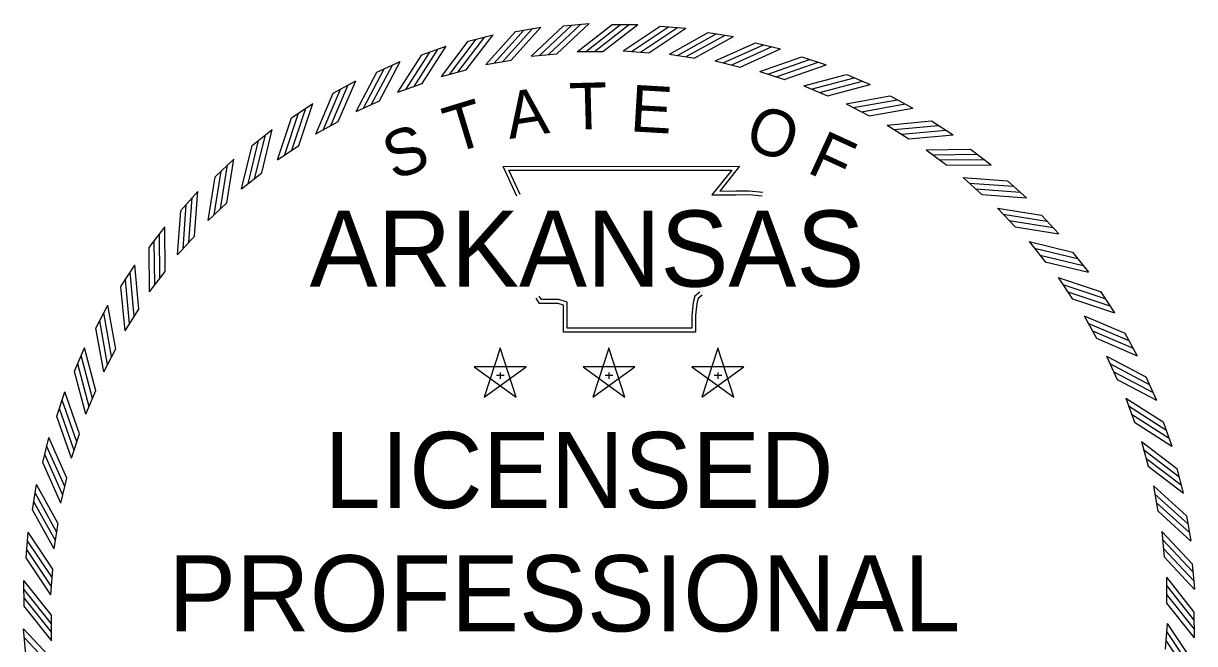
# Model space of a CAD drawing. Extents: x -129 to 14744569, y -102 to 1829048.
# Drawn here: x -104.853 to -102.787, y -99.681 to -98.587 of the extents above; entities that cross this region are included whole.
import ezdxf

# ---------------------------------------------------------------- set-up
doc = ezdxf.new("R2010")
doc.units = 0
doc.layers.add('STAMP', color=7, linetype='Continuous')

msp = doc.modelspace()

# ---------------------------------------------------------------- linework, layer by layer
at = {"layer": 'STAMP'}
for p, q in [((-103.9843, -98.6012), (-103.9398, -98.5934)), ((-103.8996, -98.5911), (-103.8546, -98.587)), ((-103.814, -98.5886), (-103.7687, -98.5886)), ((-103.7292, -98.592), (-103.6841, -98.5953)), ((-104.0679, -98.6183), (-104.0241, -98.6068)), ((-103.6447, -98.603), (-103.6, -98.61)), ((-104.1497, -98.6422), (-104.1071, -98.6272)), ((-103.8757, -98.6367), (-103.8304, -98.6367)), ((-103.7943, -98.6355), (-103.7491, -98.6388)), ((-103.5613, -98.6209), (-103.5173, -98.6316)), ((-104.2293, -98.6728), (-104.1881, -98.6543)), ((-104.0368, -98.6594), (-103.9921, -98.6515)), ((-103.9567, -98.6447), (-103.9115, -98.6406)), ((-103.7131, -98.6409), (-103.6683, -98.648)), ((-103.6327, -98.6531), (-103.5886, -98.6638)), ((-103.4797, -98.6457), (-103.4368, -98.66)), ((-104.1153, -98.6806), (-104.0715, -98.669)), ((-103.5535, -98.6718), (-103.5104, -98.6861)), ((-103.4004, -98.6771), (-103.3588, -98.6948)), ((-104.3061, -98.7099), (-104.2665, -98.688)), ((-104.1919, -98.7082), (-104.1491, -98.6931)), ((-103.4761, -98.697), (-103.4344, -98.7149)), ((-103.324, -98.7149), (-103.284, -98.7361)), ((-104.3796, -98.7532), (-104.342, -98.7281)), ((-104.2659, -98.7421), (-104.2245, -98.7235)), ((-103.4011, -98.7286), (-103.361, -98.7498)), ((-104.3368, -98.7819), (-104.2972, -98.76)), ((-103.2509, -98.7589), (-103.2128, -98.7833)), ((-104.4493, -98.8024), (-104.4138, -98.7743)), ((-103.3289, -98.7662), (-103.2907, -98.7906)), ((-104.4043, -98.8275), (-104.3665, -98.8023)), ((-103.2601, -98.8096), (-103.224, -98.8371)), ((-103.1818, -98.8088), (-103.1458, -98.8363)), ((-104.5146, -98.8572), (-104.4816, -98.8262)), ((-104.4677, -98.8784), (-104.4322, -98.8503)), ((-103.1951, -98.8586), (-103.1614, -98.889)), ((-103.117, -98.8643), (-103.0834, -98.8946)), ((-104.5752, -98.9171), (-104.5449, -98.8836)), ((-104.5267, -98.9345), (-104.4936, -98.9035)), ((-103.1344, -98.9128), (-103.1033, -98.9459)), ((-103.057, -98.9249), (-103.0261, -98.9579)), ((-104.6307, -98.9819), (-104.6032, -98.946)), ((-104.5809, -98.9952), (-104.5505, -98.9616)), ((-103.0783, -98.9718), (-103.0501, -99.0073)), ((-103.0022, -98.9902), (-102.9741, -99.0257)), ((-104.6806, -99.0511), (-104.6562, -99.013)), ((-104.6299, -99.0602), (-104.6024, -99.0242)), ((-103.0273, -99.0352), (-103.0022, -99.073)), ((-102.953, -99.0599), (-102.9279, -99.0975)), ((-104.7246, -99.1241), (-104.7034, -99.0841)), ((-104.6733, -99.129), (-104.6489, -99.0908)), ((-102.9818, -99.1027), (-102.9598, -99.1423)), ((-102.9097, -99.1334), (-102.8879, -99.173)), ((-104.7624, -99.2005), (-104.7447, -99.1589)), ((-104.7109, -99.2012), (-104.6897, -99.1611)), ((-104.0117, -99.1594), (-104.04, -99.2462)), ((-103.9835, -99.2462), (-104.0116, -99.1593)), ((-103.8198, -99.1594), (-103.8481, -99.2462)), ((-103.7916, -99.2462), (-103.8197, -99.1593)), ((-103.6279, -99.1594), (-103.6562, -99.2462)), ((-103.5997, -99.2462), (-103.6278, -99.1593)), ((-102.9419, -99.1736), (-102.9233, -99.215)), ((-103.966, -99.1926), (-104.0574, -99.1925)), ((-104.0573, -99.1926), (-103.9835, -99.2463)), ((-104.0399, -99.2462), (-103.9659, -99.1926)), ((-103.7741, -99.1926), (-103.8655, -99.1925)), ((-103.8654, -99.1926), (-103.7916, -99.2463)), ((-103.848, -99.2462), (-103.774, -99.1926)), ((-103.5822, -99.1926), (-103.6736, -99.1925)), ((-103.6735, -99.1926), (-103.5997, -99.2463)), ((-103.6561, -99.2462), (-103.5821, -99.1926)), ((-104.0182, -99.2071), (-104.0046, -99.2071)), ((-104.0116, -99.2023), (-104.0116, -99.2137)), ((-103.8263, -99.2071), (-103.8127, -99.2071)), ((-103.8197, -99.2023), (-103.8197, -99.2137)), ((-103.6344, -99.2071), (-103.6208, -99.2071)), ((-103.6278, -99.2023), (-103.6278, -99.2137)), ((-102.8727, -99.2102), (-102.8541, -99.2514)), ((-104.7939, -99.2798), (-104.7796, -99.2369)), ((-104.7425, -99.2762), (-104.7246, -99.2345)), ((-102.9081, -99.2476), (-102.8929, -99.2904)), ((-102.8421, -99.2898), (-102.827, -99.3324)), ((-104.8186, -99.3614), (-104.8079, -99.3175)), ((-104.7677, -99.3536), (-104.7534, -99.3106)), ((-102.8804, -99.3242), (-102.8689, -99.368)), ((-102.8182, -99.3716), (-102.8067, -99.4154)), ((-104.8365, -99.4448), (-104.8295, -99.4001)), ((-104.7864, -99.4328), (-104.7757, -99.3887)), ((-102.8592, -99.4028), (-102.8514, -99.4474)), ((-102.8011, -99.4552), (-102.7932, -99.4997)), ((-104.8475, -99.5294), (-104.8442, -99.4843)), ((-104.7986, -99.5133), (-104.7915, -99.4685)), ((-102.8446, -99.4828), (-102.8404, -99.528)), ((-102.791, -99.5399), (-102.7868, -99.5849)), ((-104.8515, -99.6146), (-104.8519, -99.5693)), ((-104.804, -99.5945), (-104.8007, -99.5493)), ((-102.8366, -99.5638), (-102.8362, -99.6091)), ((-104.8028, -99.6759), (-104.8032, -99.6305)), ((-102.7879, -99.6251), (-102.7875, -99.6703)), ((-102.8353, -99.6452), (-102.8387, -99.6904)), ((-104.8484, -99.6998), (-104.8525, -99.6547))]:
    msp.add_line(p, q, dxfattribs=at)
for points in [[(-104.007, -98.654), (-103.9546, -98.5958)], [(-103.9922, -98.6515), (-103.9397, -98.5934)], [(-103.9567, -98.6448), (-103.8997, -98.5912)], [(-103.9422, -98.6436), (-103.8852, -98.59)], [(-103.9266, -98.6418), (-103.8696, -98.5882)], [(-103.9116, -98.6405), (-103.8546, -98.5869)], [(-103.8758, -98.6368), (-103.814, -98.5886)], [(-103.8612, -98.6369), (-103.7995, -98.5888)], [(-103.8455, -98.6366), (-103.7838, -98.5884)], [(-103.8304, -98.6367), (-103.7687, -98.5886)], [(-103.7944, -98.6355), (-103.7293, -98.592)], [(-103.7799, -98.6367), (-103.7148, -98.5932)], [(-103.7642, -98.6375), (-103.6991, -98.594)], [(-103.7492, -98.6388), (-103.6841, -98.5953)], [(-104.1154, -98.6806), (-104.0679, -98.6184)], [(-104.1013, -98.6771), (-104.0538, -98.6148)], [(-104.0861, -98.6727), (-104.0387, -98.6105)], [(-104.0715, -98.669), (-104.0241, -98.6068)], [(-104.0368, -98.6594), (-103.9844, -98.6013)], [(-104.0224, -98.657), (-103.97, -98.5989)], [(-103.7132, -98.641), (-103.6447, -98.603)], [(-103.6988, -98.6434), (-103.6304, -98.6054)], [(-103.6833, -98.6455), (-103.6148, -98.6075)], [(-103.6684, -98.6479), (-103.5999, -98.61)], [(-104.1781, -98.7035), (-104.136, -98.6376)], [(-104.1634, -98.698), (-104.1213, -98.632)], [(-104.1492, -98.6931), (-104.107, -98.6271)], [(-103.6327, -98.6531), (-103.5614, -98.6209)], [(-103.6186, -98.6567), (-103.5472, -98.6245)], [(-103.6033, -98.6601), (-103.5319, -98.6279)], [(-103.5886, -98.6638), (-103.5173, -98.6316)], [(-104.2384, -98.7295), (-104.2018, -98.6603)], [(-104.2246, -98.7234), (-104.188, -98.6542)], [(-104.1919, -98.7083), (-104.1498, -98.6423)], [(-103.5535, -98.6718), (-103.4798, -98.6457)], [(-103.5398, -98.6766), (-103.466, -98.6504)], [(-103.5247, -98.6812), (-103.451, -98.655)], [(-103.5105, -98.6861), (-103.4367, -98.6599)], [(-104.2659, -98.7421), (-104.2294, -98.6729)], [(-104.2526, -98.7363), (-104.216, -98.667)], [(-103.4762, -98.6971), (-103.4005, -98.6771)], [(-104.3105, -98.7671), (-104.2798, -98.6951)], [(-104.2972, -98.7599), (-104.2665, -98.6879)], [(-103.4628, -98.7029), (-103.3871, -98.6829)], [(-103.4482, -98.7088), (-103.3726, -98.6888)], [(-103.4344, -98.7148), (-103.3588, -98.6948)], [(-104.3369, -98.782), (-104.3062, -98.71)], [(-104.3241, -98.775), (-104.2934, -98.703)], [(-103.4011, -98.7286), (-103.3241, -98.7149)], [(-103.3883, -98.7355), (-103.3112, -98.7218)], [(-104.3792, -98.8106), (-104.3546, -98.7363)], [(-104.3666, -98.8023), (-104.3419, -98.728)], [(-103.3743, -98.7426), (-103.2972, -98.7289)], [(-103.361, -98.7497), (-103.2839, -98.7361)], [(-104.4043, -98.8275), (-104.3796, -98.7532)], [(-104.3921, -98.8196), (-104.3674, -98.7453)], [(-103.329, -98.7662), (-103.251, -98.7589)], [(-104.4441, -98.8595), (-104.4257, -98.7835)], [(-104.4322, -98.8503), (-104.4138, -98.7742)], [(-103.3168, -98.7742), (-103.2388, -98.7669)], [(-103.3033, -98.7823), (-103.2254, -98.7751)], [(-103.2907, -98.7906), (-103.2128, -98.7833)], [(-104.4677, -98.8785), (-104.4493, -98.8024)], [(-104.4562, -98.8696), (-104.4378, -98.7935)], [(-103.2601, -98.8096), (-103.1819, -98.8088)], [(-103.2487, -98.8186), (-103.1704, -98.8178)], [(-104.5048, -98.9137), (-104.4927, -98.8364)], [(-104.4937, -98.9035), (-104.4816, -98.8262)], [(-103.9825, -98.8914), (-104.0066, -98.8392), (-103.5894, -98.8389), (-103.6243, -98.8827), (-103.5959, -98.8824), (-103.5722, -98.882), (-103.5486, -98.8846)], [(-103.9765, -98.8886), (-103.9963, -98.8458), (-103.6031, -98.8455), (-103.6381, -98.8895), (-103.5958, -98.889), (-103.5726, -98.8887), (-103.5493, -98.8912)], [(-103.236, -98.8278), (-103.1577, -98.827)], [(-103.2241, -98.8371), (-103.1458, -98.8363)], [(-104.5267, -98.9346), (-104.5146, -98.8572)], [(-104.516, -98.9247), (-104.5039, -98.8474)], [(-103.1951, -98.8586), (-103.1171, -98.8643)], [(-104.5506, -98.9616), (-104.5449, -98.8835)], [(-103.1844, -98.8685), (-103.1064, -98.8741)], [(-103.1725, -98.8787), (-103.0945, -98.8844)], [(-104.571, -98.9846), (-104.5654, -98.9065)], [(-104.5608, -98.9727), (-104.5551, -98.8946)], [(-103.1615, -98.8889), (-103.0834, -98.8946)], [(-104.5809, -98.9953), (-104.5752, -98.9172)], [(-103.1344, -98.9128), (-103.0571, -98.9249)], [(-103.1246, -98.9235), (-103.0472, -98.9356)], [(-104.6024, -99.0242), (-104.6032, -98.9459)], [(-103.1136, -98.9347), (-103.0362, -98.9468)], [(-103.1033, -98.9458), (-103.026, -98.9579)], [(-104.6209, -99.0488), (-104.6217, -98.9705)], [(-104.6117, -99.0361), (-104.6125, -98.9578)], [(-104.6299, -99.0603), (-104.6307, -98.982)], [(-103.0784, -98.9718), (-103.0023, -98.9902)], [(-103.0694, -98.9833), (-102.9934, -99.0017)], [(-103.0594, -98.9954), (-102.9833, -99.0138)], [(-103.0501, -99.0073), (-102.9741, -99.0257)], [(-104.6572, -99.1035), (-104.6644, -99.0256)], [(-104.6489, -99.0909), (-104.6562, -99.0129)], [(-104.6733, -99.1291), (-104.6806, -99.0512)], [(-104.6654, -99.1169), (-104.6726, -99.039)], [(-103.0274, -99.0352), (-102.9531, -99.0599)], [(-103.0194, -99.0474), (-102.9451, -99.0721)], [(-103.6551, -99.0662), (-103.6623, -99.072), (-103.6646, -99.0807), (-103.667, -99.1023), (-103.667, -99.1312), (-103.8999, -99.1312), (-103.8999, -99.0922), (-103.8999, -99.0836), (-103.9093, -99.0807), (-103.9425, -99.0807), (-103.9484, -99.0717)], [(-103.6593, -99.0611), (-103.6681, -99.0682), (-103.6711, -99.0794), (-103.6736, -99.102), (-103.6736, -99.1245), (-103.8933, -99.1245), (-103.8933, -99.0922), (-103.8933, -99.0787), (-103.9084, -99.0741), (-103.9389, -99.0741), (-103.9428, -99.0681)], [(-103.0104, -99.0603), (-102.9361, -99.0849)], [(-103.0022, -99.0729), (-102.9279, -99.0976)], [(-104.6898, -99.1612), (-104.7034, -99.0841)], [(-104.704, -99.1885), (-104.7177, -99.1114)], [(-104.697, -99.1744), (-104.7106, -99.0973)], [(-102.9818, -99.1026), (-102.9098, -99.1333)], [(-104.7109, -99.2013), (-104.7246, -99.1242)], [(-102.9749, -99.1154), (-102.9029, -99.1462)], [(-102.967, -99.129), (-102.895, -99.1597)], [(-102.9598, -99.1423), (-102.8878, -99.173)], [(-104.7307, -99.2484), (-104.7507, -99.1727)], [(-104.7247, -99.2346), (-104.7447, -99.1589)], [(-102.942, -99.1736), (-102.8728, -99.2101)], [(-104.7366, -99.263), (-104.7566, -99.1873)], [(-102.9361, -99.1869), (-102.8669, -99.2235)], [(-104.7424, -99.2763), (-104.7624, -99.2006)], [(-102.9294, -99.2011), (-102.8601, -99.2377)], [(-102.9233, -99.2149), (-102.8541, -99.2515)], [(-104.7534, -99.3106), (-104.7796, -99.2369)], [(-104.7583, -99.3249), (-104.7845, -99.2511)], [(-102.9081, -99.2476), (-102.8422, -99.2897)], [(-104.7677, -99.3537), (-104.7938, -99.2799)], [(-104.7629, -99.3399), (-104.7891, -99.2661)], [(-102.9034, -99.2614), (-102.8374, -99.3035)], [(-102.8978, -99.2761), (-102.8319, -99.3182)], [(-102.8929, -99.2903), (-102.827, -99.3325)], [(-104.7757, -99.3888), (-104.8079, -99.3174)], [(-104.7794, -99.4034), (-104.8116, -99.332)], [(-102.8805, -99.3241), (-102.8182, -99.3716)], [(-102.8769, -99.3383), (-102.8147, -99.3857)], [(-104.7864, -99.4329), (-104.8186, -99.3615)], [(-104.7828, -99.4188), (-104.815, -99.3474)], [(-102.8726, -99.3534), (-102.8103, -99.4008)], [(-102.8689, -99.368), (-102.8066, -99.4154)], [(-104.7916, -99.4685), (-104.8295, -99.4001)], [(-102.8593, -99.4027), (-102.8012, -99.4551)], [(-104.794, -99.4834), (-104.832, -99.4149)], [(-102.8569, -99.4171), (-102.7988, -99.4695)], [(-104.7985, -99.5133), (-104.8365, -99.4449)], [(-104.7961, -99.499), (-104.8341, -99.4305)], [(-102.8538, -99.4325), (-102.7957, -99.4849)], [(-102.8513, -99.4474), (-102.7932, -99.4998)], [(-104.8007, -99.5493), (-104.8442, -99.4842)], [(-102.8446, -99.4828), (-102.791, -99.5398)], [(-104.802, -99.5643), (-104.8455, -99.4992)], [(-102.8434, -99.4973), (-102.7898, -99.5543)], [(-104.8028, -99.58), (-104.8463, -99.5149)], [(-102.8416, -99.5129), (-102.788, -99.5699)], [(-102.8404, -99.5279), (-102.7868, -99.585)], [(-104.804, -99.5945), (-104.8475, -99.5294)], [(-104.8032, -99.6306), (-104.8519, -99.5693)], [(-102.8366, -99.5637), (-102.7879, -99.625)], [(-104.8032, -99.6456), (-104.8519, -99.5844)], [(-102.8366, -99.5783), (-102.7879, -99.6396)], [(-104.8027, -99.6613), (-104.8514, -99.6001)], [(-102.8362, -99.594), (-102.7874, -99.6553)], [(-102.8362, -99.6091), (-102.7874, -99.6704)], [(-104.8027, -99.6759), (-104.8514, -99.6146)], [(-102.8354, -99.6451), (-102.7919, -99.7102)], [(-104.799, -99.7117), (-104.8526, -99.6547)], [(-104.7977, -99.7268), (-104.8513, -99.6697)], [(-102.8366, -99.6596), (-102.7931, -99.7247)], [(-102.8374, -99.6753), (-102.7939, -99.7404)]]:
    msp.add_lwpolyline(points, dxfattribs=at)

# ---------------------------------------------------------------- texts
for s, rotation, p in [('T', 1.4789, (-103.889, -98.7746)), ('E', 356.672, (-103.7836, -98.7771)), ('T', 16.9015, (-104.0952, -98.817)), ('A', 8.6788, (-103.9952, -98.7909)), ('O', 341.2218, (-103.5838, -98.8053)), ('S', 19.7726, (-104.1998, -98.864)), ('F', 335.3628, (-103.4729, -98.8487))]:
    msp.add_text(s, height=0.0823, rotation=rotation, dxfattribs=at).set_placement(p)
for s, height, p in [('ARKANSAS', 0.13433, (-104.3477, -99.0512)), ('LICENSED', 0.13433, (-104.3221, -99.4417)), ('PROFESSIONAL', 0.134326, (-104.5972, -99.6591))]:
    msp.add_text(s, height=height, dxfattribs=at).set_placement(p)

doc.saveas('drawing.dxf')
